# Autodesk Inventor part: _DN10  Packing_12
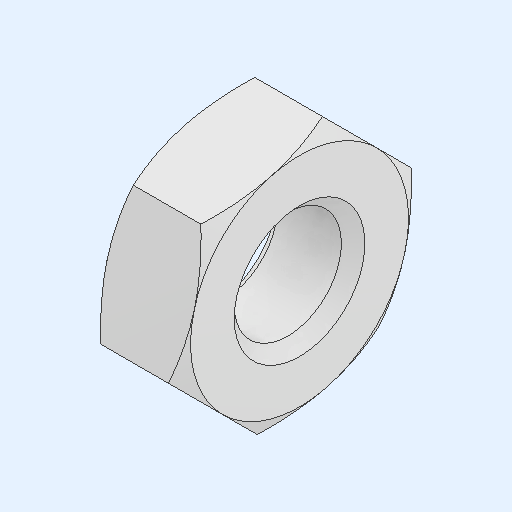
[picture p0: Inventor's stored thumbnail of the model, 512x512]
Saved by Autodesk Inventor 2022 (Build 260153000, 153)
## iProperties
Created: 2021-12
Part Number: _DN10  Packing_12
Material: Generico
Document SubType Name: Modeling
Designer: admin
Density: 1 g/cm^3
Appearance: Default
Author: admin
Revision Number: NONE
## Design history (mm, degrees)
feature "_DN10  Packing"
node "Solido1"
